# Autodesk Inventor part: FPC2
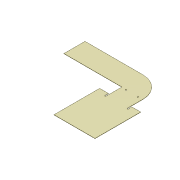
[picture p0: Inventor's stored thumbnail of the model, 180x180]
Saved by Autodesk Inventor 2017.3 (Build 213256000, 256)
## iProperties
Part Number: FPC2
Material: ポリプロピレン
Document SubType Name: Modeling
Designer: kyushu-hep
Density: 0.899 g/cm^3
Appearance: 滑らか - 灰色
Mass: 0.483015 g
Surface Area: 54.372 cm^2
Volume: 0.53728 cm^3
Author: kyushu-hep
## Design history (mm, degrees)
sketch "スケッチ1"
  geometry: L1 (-4.606, 13.906)-(-4.606, -25.094); L2 (-4.606, -25.094)-(30.394, -25.094); L3 (30.394, -25.094)-(30.394, 13.906); L4 (30.394, 13.906)-(22.894, 13.906); L5 (22.894, 13.906)-(22.894, 10.906); L6 (21.894, 10.906)-(21.894, 24.406); L7 (3.894, 42.406)-(-45.606, 42.406); L8 (-45.606, 42.406)-(-45.606, 24.406); L9 (-45.606, 24.406)-(3.894, 24.406); L10 (3.894, 24.406)-(3.894, 10.906); L11 (2.894, 10.906)-(2.894, 13.906); L12 (2.894, 13.906)-(-4.606, 13.906); A1 r 0.5 centre (22.394, 10.906) between (21.894, 10.906) and (22.894, 10.906); A2 r 18 centre (3.894, 24.406) between (21.894, 24.406) and (3.894, 42.406); A3 r 0.5 centre (3.394, 10.906) between (2.894, 10.906) and (3.894, 10.906); 1 further point
  constraints: 24 end point, 8 perpendicular, 6 point on circle, 6 tangent, 3 centre point, 3 equal length, 2 parallel, 1 horizontal, 1 vertical
  dimensions: "d0" = 39 distance of L1.start L1.end; "d1" = 35 distance of L1.end L2.end; "d2" = 39 distance of L2.end L3.end; "d3" = 13.5 distance of L6.start L6.end; "d4" = 0.5 distance from line of L10 A3.centre; "d5" = 0.5 distance from line of L6 A1.centre; "d6" = 18 distance between parallel lines of L6 L10; "d7" = 3 distance of L4.end L5.end; "d8" = 18 distance from line of L6 A2.centre; "d9" = 76 distance between parallel lines of L3 L8
extrude "押し出し1" new body sketch "スケッチ1" distance "d10" = 0.2; taper "d11" = 0 deg
sketch "スケッチ2"
  geometry: L1 (-4.606, -25.094)-(30.394, -25.094) reference; L2 (3.894, 24.406)-(3.894, 10.906) reference; C1 r 0.5 at (7.844, 23.906); C2 r 0.5 at (17.944, 23.906); 1 further point
  constraints: 2 centre point
  dimensions: "d12" = 1 diameter of C1; "d13" = 1 diameter of C2; "d14" = 49 distance from line of C1.centre L1; "d15" = 49 distance from line of C2.centre L1; "d16" = 10.1 distance of C2.centre C1.centre; "d17" = 3.95 distance from line of C1.centre L2
extrude "押し出し2" cut sketch "スケッチ2" distance "d18" = 0.2; taper "d19" = 0 deg
node "ソリッド1"
